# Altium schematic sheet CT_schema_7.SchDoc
size 427 x 414 mm
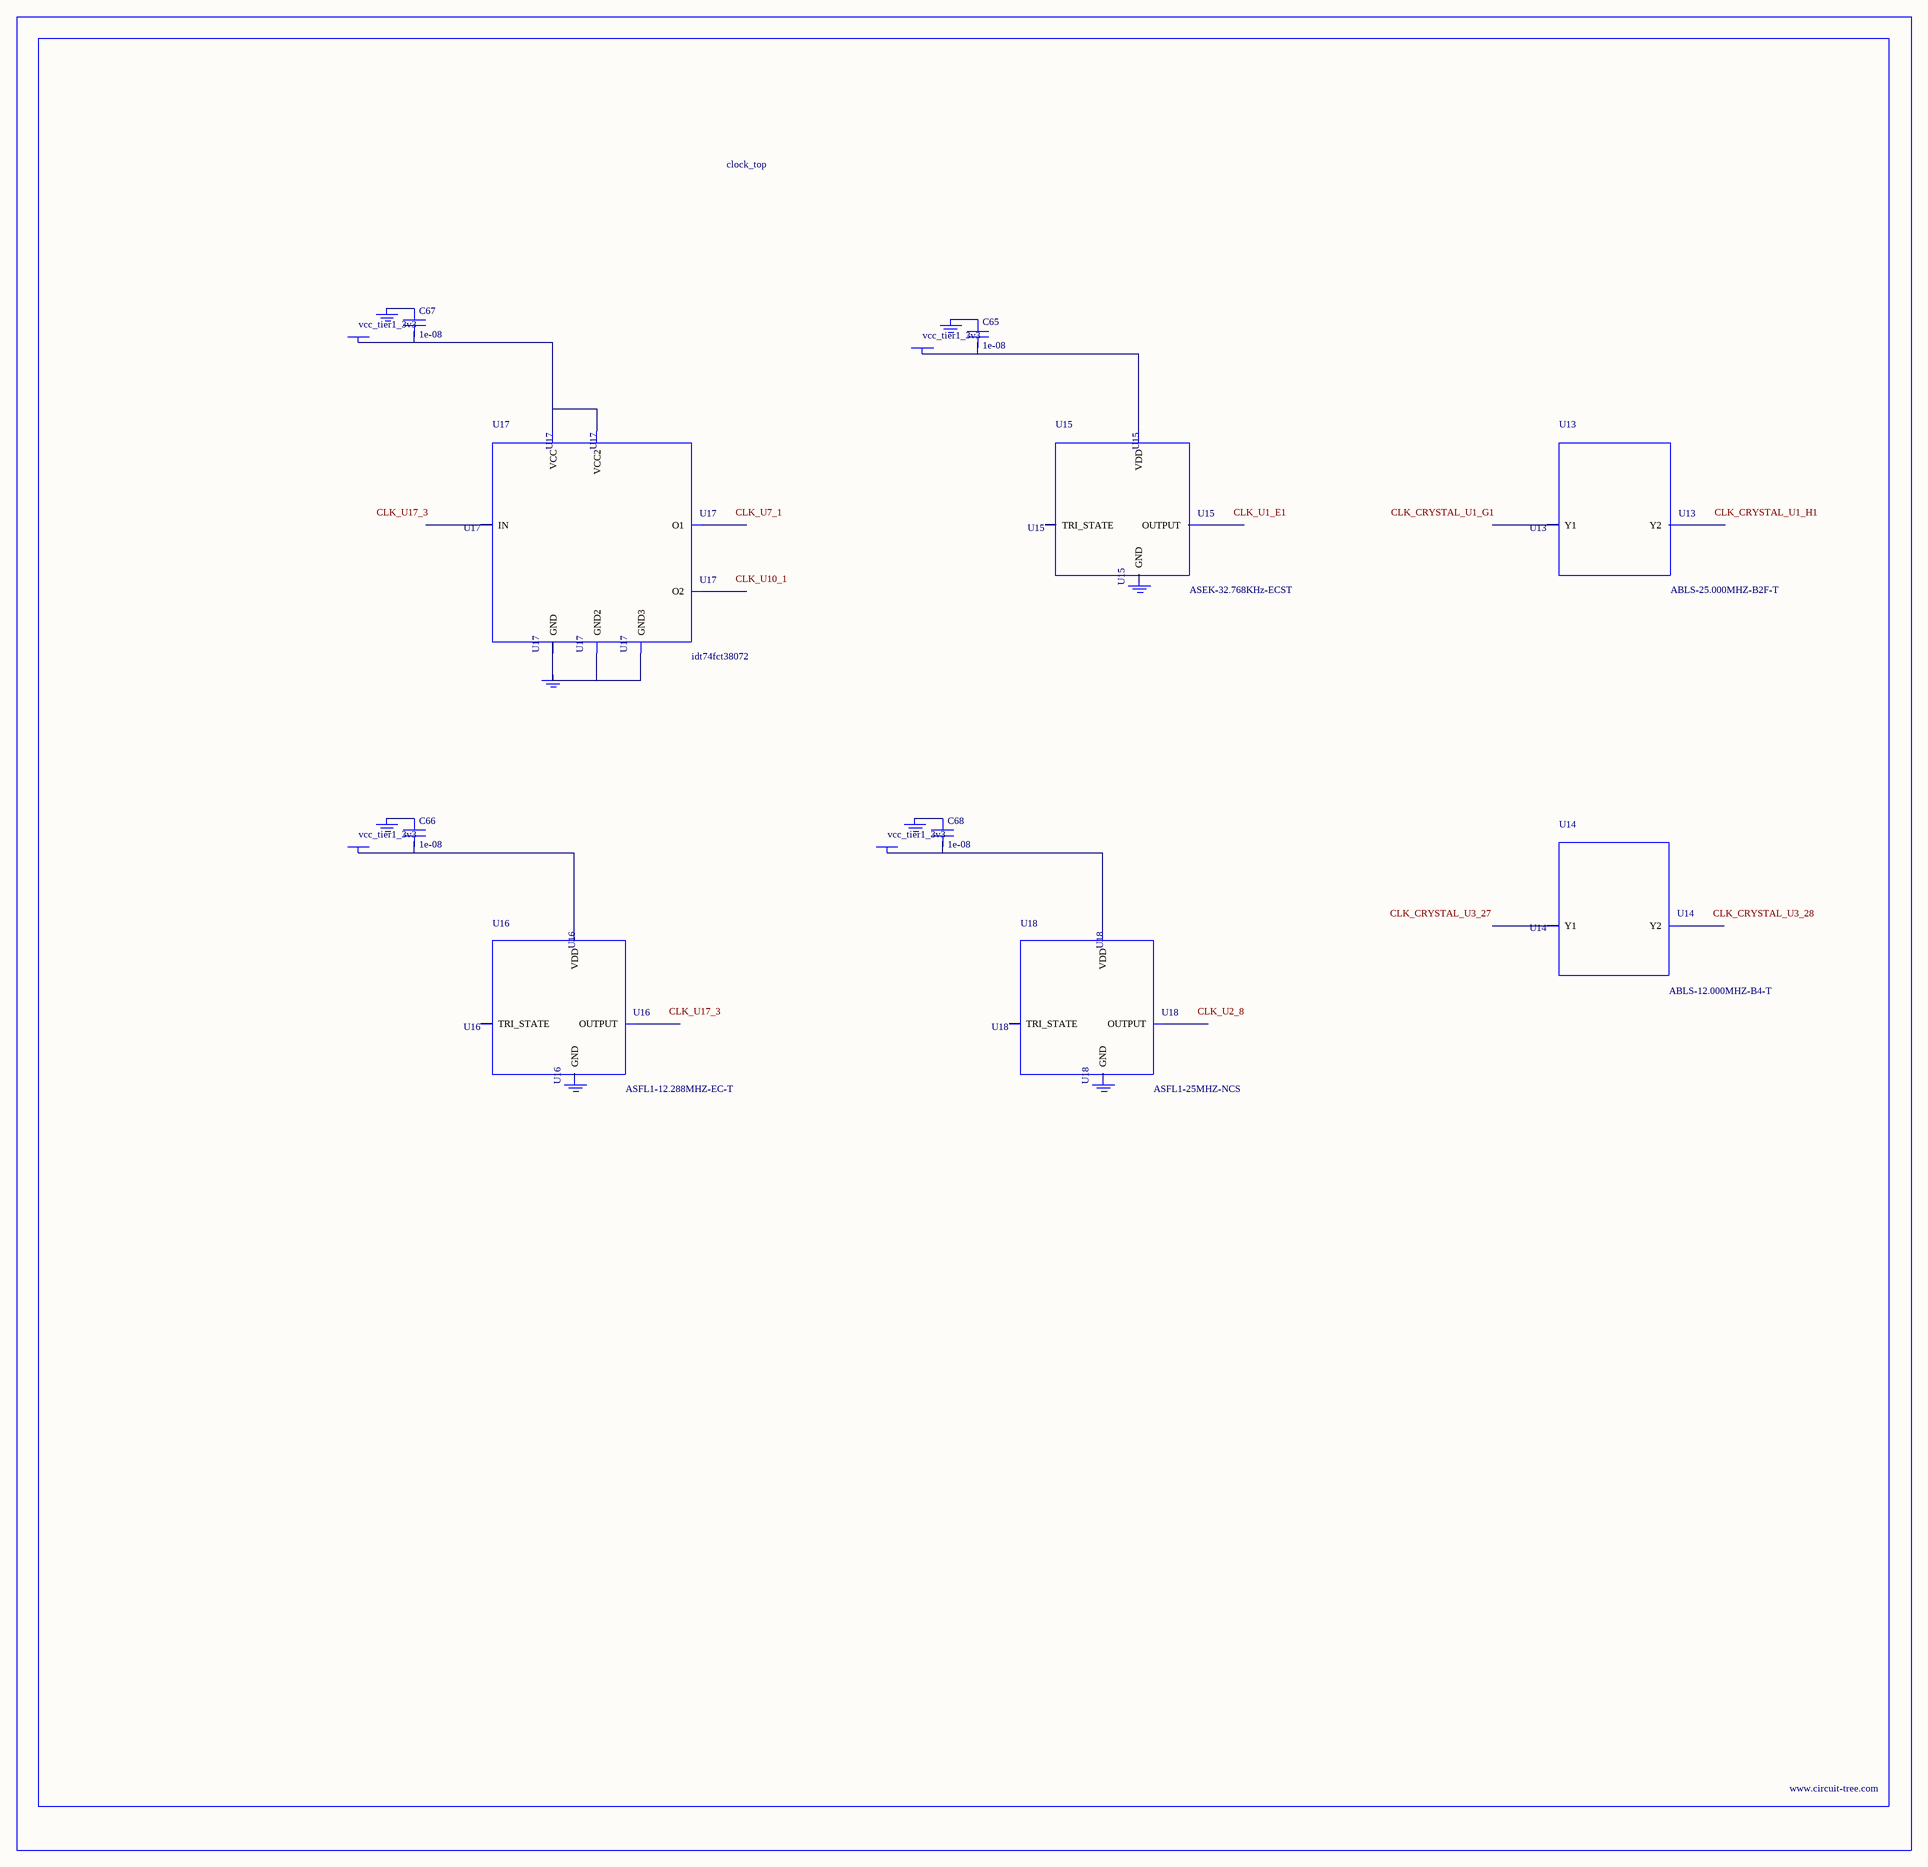
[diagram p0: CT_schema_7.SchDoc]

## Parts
BORDER6  (no value)
C65  1e-08  [C0402]
C66  1e-08  [C0402]
C67  1e-08  [C0402]
C68  1e-08  [C0402]
GND_INSTANCE_6_0  (no value)
GND_INSTANCE_6_1  (no value)
GND_INSTANCE_6_2  (no value)
GND_INSTANCE_6_3  (no value)
GND_INSTANCE_6_4  (no value)
GND_INSTANCE_6_5  (no value)
GND_INSTANCE_6_6  (no value)
GND_INSTANCE_6_7  (no value)
POWER_INSTANCE_6_0  vcc_tier1_3v3
POWER_INSTANCE_6_1  vcc_tier1_3v3
POWER_INSTANCE_6_2  vcc_tier1_3v3
POWER_INSTANCE_6_3  vcc_tier1_3v3
U13  ABLS-25.000MHZ-B2F-T  [ABLS-25.000MHZ-B2F-T]
U14  ABLS-12.000MHZ-B4-T  [ABLS-12.000MHZ-B4-T]
U15  ASEK-32.768KHz-ECST  [ASEK]
U16  ASFL1-12.288MHZ-EC-T  [ASFL1]
U17  idt74fct38072  [IDT74FCT38072]
U18  ASFL1-25MHZ-NCS  [ASFL1]

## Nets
NetC65_1: C65.1 GND_INSTANCE_6_0.0(GND)
NetC65_2: C65.2 POWER_INSTANCE_6_0.0(PWR) U15.4(VDD)
NetC66_1: C66.1 GND_INSTANCE_6_2.0(GND)
NetC66_2: C66.2 POWER_INSTANCE_6_1.0(PWR) U16.4(VDD)
NetC67_1: C67.1 GND_INSTANCE_6_4.0(GND)
NetC67_2: C67.2 POWER_INSTANCE_6_2.0(PWR) U17.1(VCC) U17.2(VCC2)
NetC68_1: C68.1 GND_INSTANCE_6_6.0(GND)
NetC68_2: C68.2 POWER_INSTANCE_6_3.0(PWR) U18.4(VDD)
NetGND_INSTANCE_6_5_0: GND_INSTANCE_6_5.0(GND) U17.4(GND) U17.5(GND2) U17.8(GND3)

Not connected (* = marked no-connect by the designer): GND_INSTANCE_6_1 0(GND); GND_INSTANCE_6_3 0(GND); GND_INSTANCE_6_7 0(GND); U13 1(Y1) 2(Y2); U14 1(Y1) 2(Y2); U15 1(TRI_STATE) 2(GND) 3(OUTPUT); U16 1(TRI_STATE) 2(GND) 3(OUTPUT); U17 3(IN) 6(O2) 7(O1); U18 1(TRI_STATE) 2(GND) 3(OUTPUT)

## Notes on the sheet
- Labels drawn without touching a wire or pin: CLK_CRYSTAL_U1_G1, CLK_CRYSTAL_U1_H1, CLK_CRYSTAL_U3_27, CLK_CRYSTAL_U3_28, CLK_U1_E1, CLK_U2_8, CLK_U7_1, CLK_U10_1, CLK_U17_3

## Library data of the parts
BORDER6 = BORDER_PAGE6
C65-C68 = C0402C103K3RAC
GND_INSTANCE_6_0-GND_INSTANCE_6_7 = GND
POWER_INSTANCE_6_0-POWER_INSTANCE_6_3 = PWR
